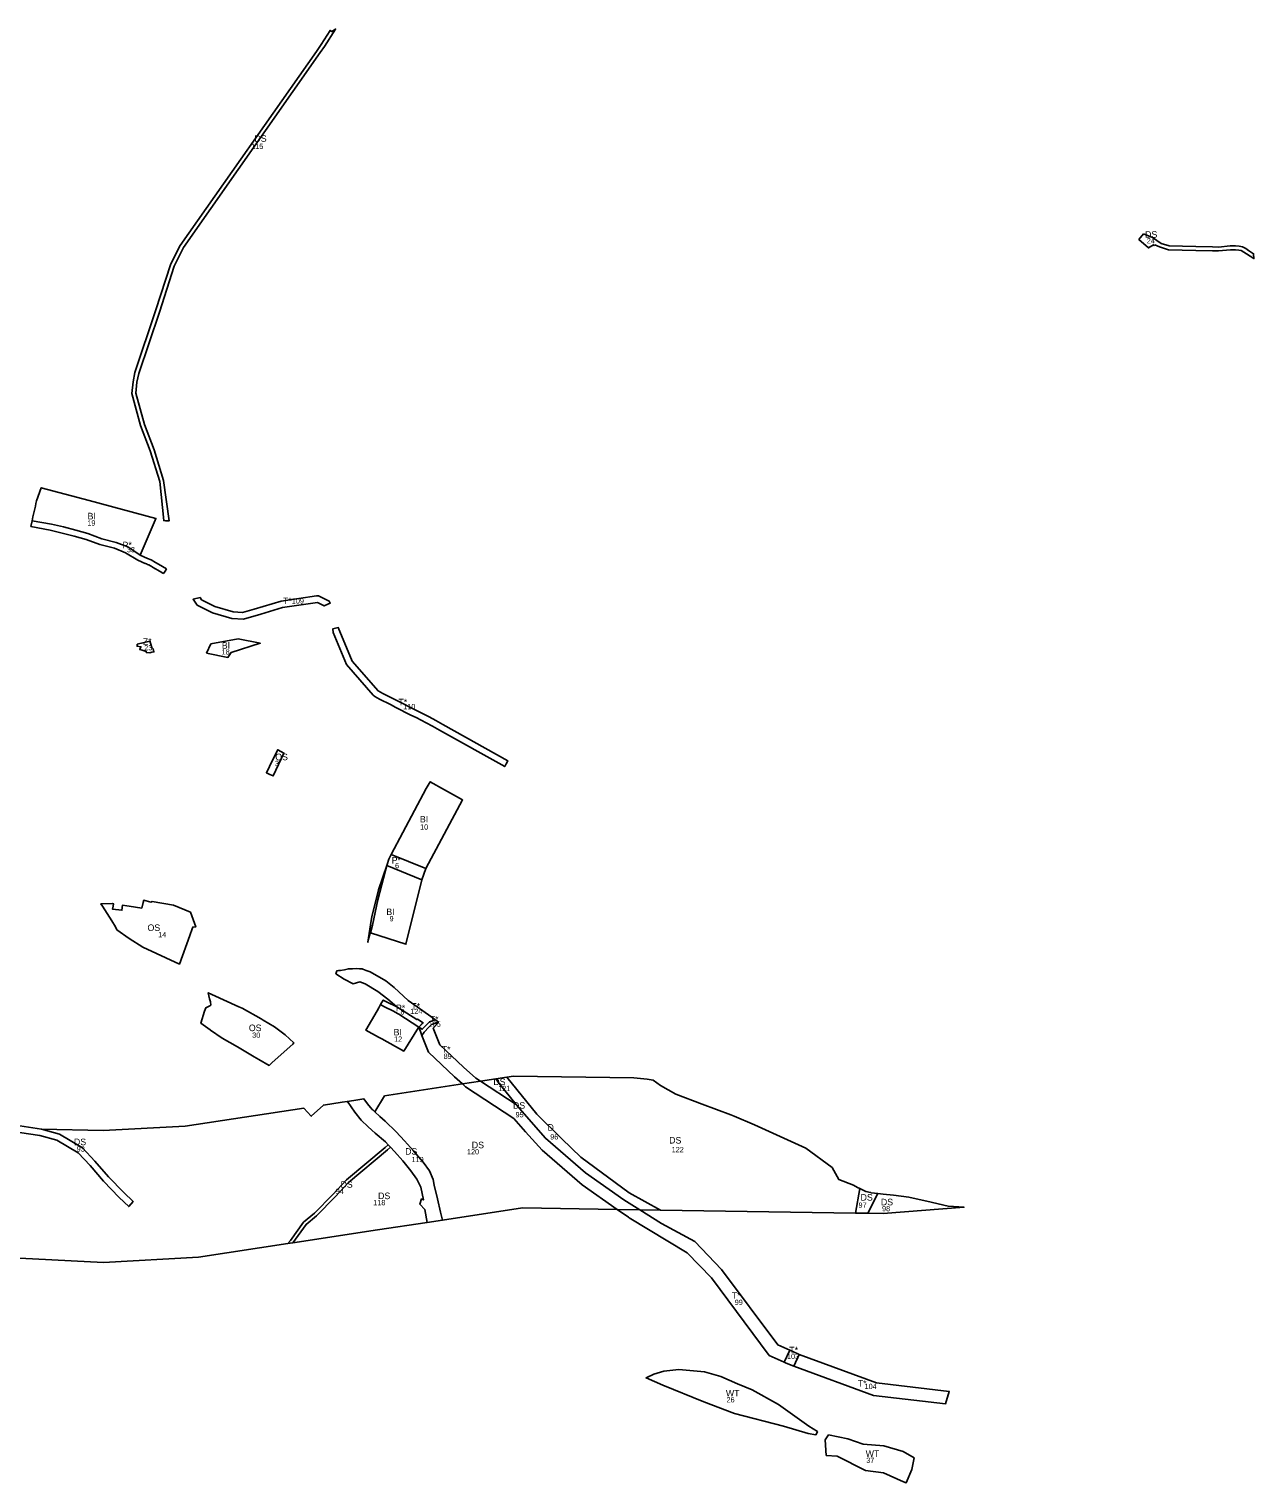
# Model space of a CAD drawing. Extents: x -521621 to -516990, y -1190025 to -1185905.
# Drawn here: x -518852 to -516990, y -1188114 to -1185905 of the extents above; entities that cross this region are included whole.
import ezdxf

# ---------------------------------------------------------------- set-up
doc = ezdxf.new("R2010")
doc.units = 0
for name, color, linetype in [('bydleni_n', 7, 'Continuous'), ('fpl_id', 7, 'Continuous'), ('s_zelen_n', 7, 'Continuous'), ('v_infrastr_n', 7, 'Continuous'), ('voda_n', 7, 'Continuous')]:
    doc.layers.add(name, color=color, linetype=linetype)

msp = doc.modelspace()

# ---------------------------------------------------------------- linework, layer by layer
at = {"layer": 'bydleni_n'}
for points in [[(-518840.4, -1186621.9), (-518833.2, -1186601.9), (-518760.6, -1186621.4), (-518659.1, -1186648.4), (-518660.2, -1186651.1), (-518682.8, -1186704.3), (-518701.7, -1186691.8), (-518719.2, -1186684.8), (-518741.4, -1186679.2), (-518762.3, -1186671.2), (-518780.7, -1186666.3), (-518799.2, -1186661.4), (-518817.9, -1186657.2), (-518847.3, -1186652.1), (-518846, -1186646.1), (-518842.2, -1186629.7), (-518841.3, -1186625.6)], [(-518582, -1186853.4), (-518575.5, -1186839.1), (-518534, -1186831.5), (-518500.5, -1186838.1), (-518544.5, -1186852.1), (-518549.5, -1186859.7)]]:
    msp.add_lwpolyline(points, close=True, dxfattribs=at)
for points in [[(-518301.3, -1187159.1), (-518248.2, -1187058.6), (-518242.1, -1187048.5), (-518220.4, -1187060.8), (-518193, -1187076.3), (-518249, -1187180.4)], [(-518249, -1187180.4), (-518301.3, -1187159.1)], [(-518254.8, -1187197.9), (-518279.2, -1187295.6), (-518333, -1187278.1), (-518329.8, -1187266.7), (-518322, -1187228), (-518310.3, -1187183.3), (-518308.2, -1187176.1)], [(-518308.2, -1187176.1), (-518254.8, -1187197.9)], [(-518320.5, -1187436.5), (-518340, -1187426.1), (-518322.8, -1187396.6), (-518320.4, -1187392.2), (-518317.7, -1187387.2), (-518317.7, -1187387.2), (-518312.4, -1187389.9), (-518296.7, -1187397.8), (-518296.3, -1187398)], [(-518296.3, -1187398), (-518290.1, -1187402), (-518259.5, -1187421.5), (-518260.1, -1187422.1), (-518282.4, -1187458), (-518315.8, -1187439.2), (-518320.5, -1187436.5)]]:
    msp.add_lwpolyline(points, dxfattribs=at)
at = {"layer": 's_zelen_n'}
msp.add_lwpolyline([(-518687.6, -1186839.4), (-518668.5, -1186834.7), (-518666.9, -1186839.5), (-518665.3, -1186844.4), (-518663.2, -1186846.4), (-518662, -1186851.2), (-518665, -1186851.9), (-518668, -1186852.7), (-518673.8, -1186852.1), (-518673.8, -1186850.6), (-518680, -1186848.7), (-518683.5, -1186847.6), (-518681.8, -1186843.4), (-518687.5, -1186842.8)], close=True, dxfattribs=at)
at = {"layer": 'v_infrastr_n'}
for points in [[(-518689.3, -1186458.1), (-518676.6, -1186505.5), (-518661.9, -1186544), (-518647.4, -1186591), (-518638.9, -1186652.2), (-518644, -1186652.1), (-518647, -1186651.6), (-518653.3, -1186592.2), (-518667.6, -1186545.9), (-518682.3, -1186507.3), (-518695.4, -1186458.6), (-518693.7, -1186440.7), (-518690.9, -1186426.8), (-518659.5, -1186333), (-518636.5, -1186261.5), (-518622.2, -1186233.6), (-518414.9, -1185939), (-518414.9, -1185939), (-518408.8, -1185929.5), (-518407.8, -1185928), (-518394.2, -1185906.7), (-518391.7, -1185908.5), (-518385.9, -1185904.8), (-518402.8, -1185931.3), (-518409.2, -1185940.6), (-518409.2, -1185940.6), (-518409.2, -1185940.6), (-518617, -1186236.6), (-518631.4, -1186265.3), (-518653.7, -1186334.8), (-518685.1, -1186428.3), (-518687.8, -1186441.6)], [(-517158.3, -1186215.8), (-517144.5, -1186221.5), (-517131.5, -1186230.4), (-517119, -1186234.4), (-517078.5, -1186235.2), (-517053.4, -1186235.8), (-517044.3, -1186236), (-517026.4, -1186234.3), (-517018.4, -1186234.3), (-517012.7, -1186234.7), (-517007.6, -1186235.8), (-517002.6, -1186238.4), (-516998.5, -1186241.1), (-516990.9, -1186246.1), (-516990.4, -1186253.6), (-517001.8, -1186246.1), (-517005.6, -1186243.6), (-517009.6, -1186241.5), (-517013.5, -1186240.7), (-517018.6, -1186240.3), (-517026.2, -1186240.3), (-517044, -1186242), (-517053.5, -1186241.8), (-517078.7, -1186241.2), (-517120, -1186240.3), (-517134.1, -1186235.8), (-517140.8, -1186232.9), (-517142.2, -1186233.7), (-517143, -1186232.4), (-517145.5, -1186234), (-517150.8, -1186237.4), (-517165.1, -1186224.3)], [(-518589.5, -1186772.2), (-518569.3, -1186782.3), (-518541.7, -1186790.6), (-518527.2, -1186791.6), (-518509.8, -1186786.4), (-518468.8, -1186774.1), (-518414.9, -1186766.3), (-518411.8, -1186765.9), (-518395.6, -1186774), (-518394.1, -1186777.2), (-518397.7, -1186778.8), (-518403.2, -1186781.3), (-518413.4, -1186776.2), (-518466.7, -1186783.9), (-518499.7, -1186793.8), (-518526.1, -1186801.7), (-518543.5, -1186800.4), (-518573, -1186791.7), (-518596.2, -1186780.1), (-518602.5, -1186771.3), (-518592, -1186768.7)], [(-518369.3, -1186870.6), (-518389.7, -1186821.6), (-518390.4, -1186816.3), (-518381.9, -1186814.2), (-518360.7, -1186865.2), (-518321.3, -1186910.5), (-518314.4, -1186914.4), (-518298.2, -1186922.5), (-518289.9, -1186926.7), (-518266.9, -1186938.3), (-518259.1, -1186942.2), (-518243.5, -1186950.1), (-518233.8, -1186955.5), (-518223, -1186961.5), (-518124.1, -1187016.9), (-518126.5, -1187021.3), (-518128.9, -1187025.6), (-518227.9, -1186970.3), (-518238.7, -1186964.2), (-518248.2, -1186958.9), (-518263.6, -1186951.1), (-518271.4, -1186947.2), (-518294.4, -1186935.6), (-518302.7, -1186931.4), (-518319.1, -1186923.2), (-518326.2, -1186919.2), (-518328.9, -1186917)], [(-518481.7, -1187015.8), (-518473.9, -1186999.9), (-518469.1, -1187002.5), (-518464.5, -1187005.1), (-518480.7, -1187039.7), (-518485.9, -1187037.4), (-518491, -1187034.9)], [(-518301.3, -1187159.1), (-518249, -1187180.4), (-518254.8, -1187197.9), (-518308.2, -1187176.1), (-518310.3, -1187183.3), (-518322, -1187228), (-518329.8, -1187266.7), (-518335.2, -1187285.8), (-518336.9, -1187292.4), (-518335.9, -1187285.7), (-518332, -1187259.4), (-518330.7, -1187254.1), (-518320.6, -1187213), (-518307.8, -1187174.6), (-518305, -1187166.2)], [(-518678.3, -1187232.1), (-518677.4, -1187228.8), (-518666.6, -1187231.7), (-518664.9, -1187230.6), (-518632.3, -1187236.3), (-518606.7, -1187246.9), (-518598.4, -1187269.2), (-518603, -1187269.4), (-518604.1, -1187272.3), (-518607.6, -1187282.1), (-518623.2, -1187325.6), (-518678.9, -1187300), (-518699.8, -1187287), (-518718.5, -1187273.4), (-518720.3, -1187269.1), (-518726.1, -1187259.9), (-518729.6, -1187254.3), (-518740, -1187237.6), (-518742.7, -1187233.9), (-518724.9, -1187233.8), (-518723.6, -1187234), (-518724.2, -1187237.6), (-518725, -1187242.2), (-518710.8, -1187244), (-518709.7, -1187236.1), (-518703.4, -1187237.1), (-518699.7, -1187237.7), (-518680.6, -1187240.7)], [(-518574.2, -1187371.7), (-518532.8, -1187390.9), (-518528.1, -1187392.9), (-518499.2, -1187408.9), (-518495.8, -1187410.8), (-518479, -1187420.8), (-518462.6, -1187433.3), (-518449.2, -1187445.4), (-518450.9, -1187447.4), (-518482.3, -1187475.4), (-518487, -1187479.6), (-518502.7, -1187470.5), (-518509.5, -1187466.5), (-518535.2, -1187451.6), (-518558.5, -1187438.3), (-518576.2, -1187425.9), (-518576.8, -1187425.4), (-518590.6, -1187415.7), (-518585.1, -1187397.4), (-518583.1, -1187392.1), (-518579.2, -1187390.1), (-518577.3, -1187389), (-518575.3, -1187388), (-518576.3, -1187383.3), (-518577.4, -1187378.7), (-518578.4, -1187374), (-518579.4, -1187369.3)], [(-518262.4, -1187410.1), (-518261.7, -1187409.4), (-518253.1, -1187414.9), (-518259.5, -1187421.5), (-518290.1, -1187402), (-518296.3, -1187398), (-518296.7, -1187397.8), (-518312.4, -1187389.9), (-518317.7, -1187387.2), (-518313.6, -1187380.3), (-518308.6, -1187382.8), (-518292.7, -1187390.8)], [(-518229.8, -1187413.7), (-518237.5, -1187423), (-518227.7, -1187448.2), (-518191.7, -1187482.4), (-518172.9, -1187498.9), (-518165.5, -1187503.5), (-518193.2, -1187507.7), (-518205.2, -1187497.2), (-518244.8, -1187459.6), (-518254.7, -1187434.1), (-518251.4, -1187428.9), (-518244.4, -1187421.8), (-518240.4, -1187417.7)], [(-518142.6, -1187500), (-518125.5, -1187497.4), (-518080.2, -1187553.9), (-518042.1, -1187591.1), (-518013.4, -1187619.1), (-517939.8, -1187673.3), (-517892.4, -1187699.4), (-517923.8, -1187698.9), (-517947.8, -1187683.7), (-518006.3, -1187642.7), (-518067, -1187590.4), (-518102.9, -1187549.4), (-518111.5, -1187538.9), (-518137.5, -1187507.1)], [(-518311.5, -1187525.7), (-518193.2, -1187507.7), (-518188.5, -1187512.3), (-518115.1, -1187560.4), (-518097.5, -1187580.5), (-518072.1, -1187608.7), (-518011.3, -1187661), (-517958.1, -1187698.4), (-518102, -1187696.1), (-518223.7, -1187714.7), (-518226.7, -1187702.5), (-518231.2, -1187682.4), (-518235.9, -1187661.6), (-518237.5, -1187652.9), (-518243.1, -1187639.9), (-518253.1, -1187626.6), (-518266.5, -1187610.8), (-518267.8, -1187609.4), (-518281, -1187594.4), (-518294.1, -1187580.8), (-518310.4, -1187564.3), (-518318.7, -1187557.1), (-518326.5, -1187550.1)], [(-518193.2, -1187507.7), (-518165.5, -1187503.5), (-518111.5, -1187538.9), (-518102.9, -1187549.4), (-518067, -1187590.4), (-518006.3, -1187642.7), (-517947.8, -1187683.7), (-517923.8, -1187698.9), (-517958.1, -1187698.4), (-518011.3, -1187661), (-518072.1, -1187608.7), (-518097.5, -1187580.5), (-518115.1, -1187560.4), (-518188.5, -1187512.3)], [(-518337.4, -1187538), (-518330.2, -1187546.5), (-518329.5, -1187547.4), (-518326.5, -1187550.1), (-518318.7, -1187557.1), (-518310.4, -1187564.3), (-518294.1, -1187580.8), (-518281, -1187594.4), (-518267.8, -1187609.4), (-518266.5, -1187610.8), (-518253.1, -1187626.6), (-518243.1, -1187639.9), (-518237.5, -1187652.9), (-518235.9, -1187661.6), (-518231.2, -1187682.4), (-518226.7, -1187702.5), (-518223.7, -1187714.7), (-518246.6, -1187718.2), (-518250.4, -1187698.8), (-518258, -1187690.3), (-518255.4, -1187682.6), (-518252.6, -1187684.1), (-518256.3, -1187664.8), (-518262.3, -1187652.3), (-518271.6, -1187639.8), (-518283.6, -1187624.5), (-518296.4, -1187610.4), (-518302.4, -1187604), (-518304.1, -1187602.2), (-518305.9, -1187600.4), (-518310, -1187596), (-518325.6, -1187582.7), (-518336.4, -1187572.9), (-518347, -1187562.8), (-518356.8, -1187550.6), (-518367.9, -1187534.7), (-518368.1, -1187534.4), (-518352.3, -1187532), (-518343, -1187530.5)], [(-518434.6, -1187717.9), (-518418.1, -1187704.4), (-518390.1, -1187675.7), (-518369.6, -1187653.8), (-518310.5, -1187604.3), (-518305.9, -1187600.4), (-518304.1, -1187602.2), (-518302.4, -1187604), (-518307, -1187607.8), (-518366.2, -1187657.5), (-518386.5, -1187679.2), (-518414.8, -1187708.1), (-518430.9, -1187721.3), (-518451.1, -1187749.3), (-518454.9, -1187749.9), (-518458.6, -1187750.5), (-518454.6, -1187745.7), (-518434.6, -1187718)], [(-517589.2, -1187666.9), (-517580.3, -1187671.2), (-517573, -1187672.9), (-517572.6, -1187673), (-517572, -1187673.1), (-517562, -1187674.2), (-517577.2, -1187704.4), (-517586.4, -1187704.3), (-517596.1, -1187704.1)], [(-517553.7, -1187675.1), (-517537.9, -1187676.9), (-517514.8, -1187680), (-517489.9, -1187685.6), (-517487.3, -1187686.2), (-517454.8, -1187693.5), (-517430.9, -1187695.3), (-517553.8, -1187704.8), (-517577.2, -1187704.4), (-517562, -1187674.2)], [(-517681.4, -1187918.8), (-517689.8, -1187936.9), (-517701, -1187932), (-517704.3, -1187930.6), (-517695.5, -1187912.6), (-517692.2, -1187914)], [(-517681.4, -1187918.8), (-517563.8, -1187961.9), (-517453.5, -1187975), (-517459.3, -1187994.2), (-517568.5, -1187981.4), (-517689.8, -1187936.9)]]:
    msp.add_lwpolyline(points, close=True, dxfattribs=at)
for points in [[(-518849, -1186660.7), (-518847.3, -1186652.1)], [(-518819.9, -1186666.5), (-518849, -1186660.7)], [(-518847.3, -1186652.1), (-518817.9, -1186657.2), (-518799.2, -1186661.4), (-518780.7, -1186666.3), (-518762.3, -1186671.2), (-518741.4, -1186679.2), (-518719.2, -1186684.8), (-518701.7, -1186691.8), (-518682.8, -1186704.3)], [(-518801.5, -1186670.6), (-518819.9, -1186666.5)], [(-518783.2, -1186675.5), (-518801.5, -1186670.6)], [(-518765.2, -1186680.3), (-518783.2, -1186675.5)], [(-518744.3, -1186688.3), (-518765.2, -1186680.3)], [(-518722.1, -1186693.8), (-518744.3, -1186688.3)], [(-518705.3, -1186700.6), (-518722.1, -1186693.8)], [(-518686.4, -1186712), (-518705.3, -1186700.6)], [(-518682.8, -1186704.3), (-518677.4, -1186706.7)], [(-518680.8, -1186714.5), (-518686.4, -1186712)], [(-518678.8, -1186715.3), (-518680, -1186714.8), (-518680.8, -1186714.5)], [(-518674.8, -1186717.1), (-518675.1, -1186716.9), (-518678.8, -1186715.3)], [(-518677.4, -1186706.7), (-518671.8, -1186709.1)], [(-518673.5, -1186717.6), (-518674.8, -1186717.1)], [(-518672.3, -1186718.1), (-518673.5, -1186717.6)], [(-518669.8, -1186719.2), (-518671.1, -1186718.7), (-518672.3, -1186718.1)], [(-518671.8, -1186709.1), (-518666.1, -1186711.6)], [(-518667.3, -1186720.7), (-518669.7, -1186719.2), (-518669.8, -1186719.2)], [(-518666.4, -1186721.2), (-518667.3, -1186720.7)], [(-518664, -1186722.5), (-518664.8, -1186722.1), (-518666.4, -1186721.2)], [(-518666.1, -1186711.6), (-518659.8, -1186715.2)], [(-518662, -1186723.7), (-518664, -1186722.5)], [(-518660, -1186724.8), (-518662, -1186723.7)], [(-518659.8, -1186725), (-518660, -1186724.8)], [(-518659.8, -1186715.2), (-518655, -1186717.9)], [(-518656, -1186727.1), (-518659.8, -1186725)], [(-518655, -1186717.9), (-518649.1, -1186721.3)], [(-518649.1, -1186721.3), (-518642.8, -1186724.9)], [(-518642.8, -1186724.9), (-518645.1, -1186728.5)], [(-518653.8, -1186728.4), (-518656, -1186727.1)], [(-518651.5, -1186729.7), (-518653.8, -1186728.4)], [(-518649.3, -1186731), (-518651.5, -1186729.7)], [(-518645.1, -1186728.5), (-518647.5, -1186732), (-518649.3, -1186731)], [(-518306.6, -1187379.1), (-518321.7, -1187367.1), (-518340.9, -1187355.7), (-518349.2, -1187352.8), (-518359.5, -1187355.9), (-518372.8, -1187348.8), (-518385.4, -1187340.4), (-518384, -1187335.7), (-518381.4, -1187335.6), (-518378.8, -1187335.5), (-518372.6, -1187334.2), (-518366.5, -1187332.9), (-518360.3, -1187332.7), (-518354.1, -1187332.4), (-518349.6, -1187332.8), (-518346.4, -1187333), (-518345, -1187333.1), (-518344.5, -1187333.3), (-518339.3, -1187335.3), (-518333.5, -1187337.4), (-518309.7, -1187351.1), (-518296.7, -1187361.5)], [(-518296.7, -1187361.5), (-518275.7, -1187381.1)], [(-518275.7, -1187381.1), (-518245, -1187402.9), (-518237.9, -1187407.9), (-518234.7, -1187410.2), (-518243.2, -1187413.5), (-518248.7, -1187419), (-518254.2, -1187424.6), (-518259.5, -1187421.5), (-518253.9, -1187415.7), (-518253.1, -1187414.9), (-518261.7, -1187409.4), (-518262.4, -1187410.1), (-518292.7, -1187390.8), (-518306.6, -1187379.1)], [(-518248.7, -1187419), (-518243.2, -1187413.5), (-518234.7, -1187410.2), (-518232.2, -1187411.9), (-518229.8, -1187413.7), (-518240.4, -1187417.7), (-518244.4, -1187421.8)], [(-518259.5, -1187421.5), (-518254.2, -1187424.6), (-518248.7, -1187419)], [(-518244.4, -1187421.8), (-518251.4, -1187428.9), (-518254.7, -1187434.1), (-518256.9, -1187428.3), (-518259.5, -1187421.5)], [(-518111.5, -1187538.9), (-518165.5, -1187503.5), (-518142.6, -1187500)], [(-518142.6, -1187500), (-518137.5, -1187507.1), (-518111.5, -1187538.9)], [(-518125.5, -1187497.4), (-518115.5, -1187495.9), (-517932.8, -1187498.8), (-517912.3, -1187500.7), (-517903.3, -1187502.1), (-517892, -1187510.1), (-517869.1, -1187523.4), (-517829, -1187538.4), (-517785.5, -1187554.6), (-517780, -1187556.7), (-517749.3, -1187570.2), (-517671.4, -1187605.2), (-517631.2, -1187635), (-517621, -1187653.2), (-517598.9, -1187661.5), (-517592.8, -1187665.3), (-517589.2, -1187666.9), (-517596.1, -1187704.1), (-517892.4, -1187699.4)], [(-517892.4, -1187699.4), (-517939.8, -1187673.3), (-518013.4, -1187619.1), (-518042.1, -1187591.1), (-518080.2, -1187553.9), (-518125.5, -1187497.4)], [(-518866.3, -1187581.6), (-518835.2, -1187586.3), (-518809.6, -1187593.3), (-518777, -1187612.5), (-518759, -1187631.9), (-518738.7, -1187655.7), (-518715.1, -1187680.2), (-518700.2, -1187694.3), (-518693.8, -1187686.5), (-518708, -1187673), (-518731.3, -1187649), (-518751.6, -1187625.3), (-518770.6, -1187604.7), (-518805.7, -1187584), (-518833.1, -1187576.5), (-518739, -1187578.8), (-518614.8, -1187572), (-518434.3, -1187544.5), (-518423, -1187557), (-518404.5, -1187539.9), (-518376.1, -1187535.6), (-518368.5, -1187534.4), (-518367.9, -1187534.7), (-518356.8, -1187550.6), (-518347, -1187562.8), (-518336.4, -1187572.9), (-518325.6, -1187582.7), (-518310, -1187596), (-518305.9, -1187600.4), (-518310.5, -1187604.3), (-518369.6, -1187653.8), (-518390.1, -1187675.7), (-518418.1, -1187704.4), (-518434.6, -1187717.9), (-518454.6, -1187745.7), (-518458.6, -1187750.5), (-518594.2, -1187771.1), (-518738.7, -1187779), (-519023.8, -1187764.4)], [(-518865.7, -1187571.6), (-518833.1, -1187576.5), (-518805.7, -1187584), (-518770.6, -1187604.7), (-518751.6, -1187625.3), (-518731.3, -1187649), (-518708, -1187673), (-518693.8, -1187686.5), (-518700.2, -1187694.3), (-518715.1, -1187680.2), (-518738.7, -1187655.7), (-518759, -1187631.9), (-518777, -1187612.5), (-518809.6, -1187593.3), (-518835.2, -1187586.3), (-518866.3, -1187581.6)], [(-518246.6, -1187718.2), (-518322.2, -1187729.7), (-518451.1, -1187749.3), (-518430.9, -1187721.3), (-518414.8, -1187708.1), (-518386.5, -1187679.2), (-518366.2, -1187657.5), (-518307, -1187607.8), (-518302.4, -1187604)], [(-518302.4, -1187604), (-518296.4, -1187610.4), (-518283.6, -1187624.5), (-518271.6, -1187639.8), (-518262.3, -1187652.3), (-518256.3, -1187664.8), (-518252.6, -1187684.1), (-518255.4, -1187682.6), (-518258, -1187690.3), (-518250.4, -1187698.8), (-518246.6, -1187718.2)], [(-517940.8, -1187710.5), (-517958.1, -1187698.4), (-517923.8, -1187698.9), (-517890.9, -1187719.9), (-517840.1, -1187747.4)], [(-517840.1, -1187747.4), (-517799.3, -1187789.7), (-517714, -1187904.5), (-517695.5, -1187912.6), (-517704.3, -1187930.6), (-517726.9, -1187920.7), (-517814.6, -1187802.6), (-517851.6, -1187764.3), (-517939.7, -1187711.3)]]:
    msp.add_lwpolyline(points, dxfattribs=at)
msp.add_arc((-517929.3, -1187694.1), 20, 234.944, 238.9499, dxfattribs=at)
at = {"layer": 'voda_n'}
for points in [[(-517864.3, -1187942), (-517825.2, -1187945.2), (-517800.5, -1187952.5), (-517775.2, -1187963.8), (-517753.1, -1187972.8), (-517713, -1187994.8), (-517667, -1188027.7), (-517653.8, -1188036), (-517654.4, -1188038.4), (-517656, -1188041), (-517667.8, -1188038.9), (-517705.4, -1188027.8), (-517779.6, -1188008.6), (-517826.1, -1187990.9), (-517888.9, -1187965.6), (-517914, -1187954.7), (-517902.2, -1187948.9), (-517887.2, -1187944.5)], [(-517584.2, -1188055.5), (-517553, -1188057.6), (-517523.4, -1188066.4), (-517506.7, -1188076.1), (-517510.1, -1188093.9), (-517519.1, -1188114.2), (-517523.1, -1188112.4), (-517553.3, -1188098.9), (-517580.7, -1188095.1), (-517623.5, -1188073.6), (-517640.4, -1188072.3), (-517642.2, -1188048.5), (-517636.8, -1188041.3), (-517607.7, -1188047.3)]]:
    msp.add_lwpolyline(points, close=True, dxfattribs=at)

# ---------------------------------------------------------------- texts
at = {"layer": 'bydleni_n'}
for p in [(-518762.9, -1186649.9), (-518558.9, -1186846.4), (-518257.9, -1187110.5), (-518308.9, -1187251.3), (-518297.8, -1187434.2)]:
    msp.add_text('BI', height=10, dxfattribs=at).set_placement(p)
at = {"layer": 'fpl_id'}
for s, p in [('115', (-518514.2, -1186087)), ('24', (-517153.1, -1186230.5)), ('19', (-518763.2, -1186659.4)), ('33', (-518703.2, -1186699.9)), ('109', (-518452.5, -1186777.8)), ('23', (-518676.8, -1186848.9)), ('18', (-518559.2, -1186855.2)), ('110', (-518283.1, -1186938.4)), ('3', (-518478.1, -1187024.8)), ('10', (-518257.5, -1187121.3)), ('6', (-518295.6, -1187180)), ('9', (-518304, -1187260.7)), ('14', (-518655.5, -1187285)), ('8', (-518287.4, -1187402.3)), ('124', (-518272.5, -1187401.5)), ('30', (-518512.7, -1187437.7)), ('105', (-518244.5, -1187421)), ('12', (-518297.1, -1187443.7)), ('89', (-518221.8, -1187469.8)), ('121', (-518138.9, -1187518.7)), ('95', (-518112.5, -1187558.6)), ('96', (-518059.8, -1187592.2)), ('93', (-518779.4, -1187610.6)), ('120', (-518186.3, -1187614.9)), ('122', (-517875.2, -1187611.6)), ('119', (-518270.6, -1187626.7)), ('94', (-518385.8, -1187675)), ('118', (-518328.7, -1187692.2)), ('97', (-517591.3, -1187696.1)), ('98', (-517555.5, -1187701.3)), ('99', (-517779.4, -1187843.7)), ('103', (-517700, -1187925.8)), ('104', (-517582.1, -1187971.5)), ('26', (-517791.9, -1187991.8)), ('37', (-517579.5, -1188083.7))]:
    msp.add_text(s, height=8, dxfattribs=at).set_placement(p)
at = {"layer": 's_zelen_n'}
msp.add_text('Z*', height=10, dxfattribs=at).set_placement((-518678.8, -1186840.5))
at = {"layer": 'v_infrastr_n'}
for s, p in [('DS', (-518509.3, -1186076.1)), ('DS', (-517155.8, -1186221.9)), ('P*', (-518709.8, -1186693.9)), ('T*', (-518465.9, -1186778.7)), ('T*', (-518290.5, -1186932.5)), ('OS', (-518477.7, -1187015.9)), ('P*', (-518300.8, -1187172.9)), ('OS', (-518671.8, -1187275.4)), ('P*', (-518294.3, -1187397.3)), ('T*', (-518270.9, -1187395)), ('T*', (-518242.9, -1187414.4)), ('OS', (-518517.8, -1187427.6)), ('T*', (-518224.7, -1187460.3)), ('DS', (-518146.3, -1187509.6)), ('DS', (-518116.4, -1187545.4)), ('D', (-518063.9, -1187578.9)), ('DS', (-517879.1, -1187598.4)), ('DS', (-518783.6, -1187600.9)), ('DS', (-518280.3, -1187615.4)), ('DS', (-518179, -1187605.6)), ('DS', (-518378.5, -1187665.6)), ('DS', (-518321.4, -1187682.9)), ('DS', (-517588.2, -1187685.2)), ('DS', (-517557.3, -1187692.3)), ('T*', (-517784, -1187834.3)), ('T*', (-517696.5, -1187917.3)), ('T*', (-517592.5, -1187967.7))]:
    msp.add_text(s, height=10, dxfattribs=at).set_placement(p)
at = {"layer": 'voda_n'}
for p in [(-517792.8, -1187982.8), (-517580.4, -1188074.6)]:
    msp.add_text('WT', height=10, dxfattribs=at).set_placement(p)

doc.saveas('drawing.dxf')
